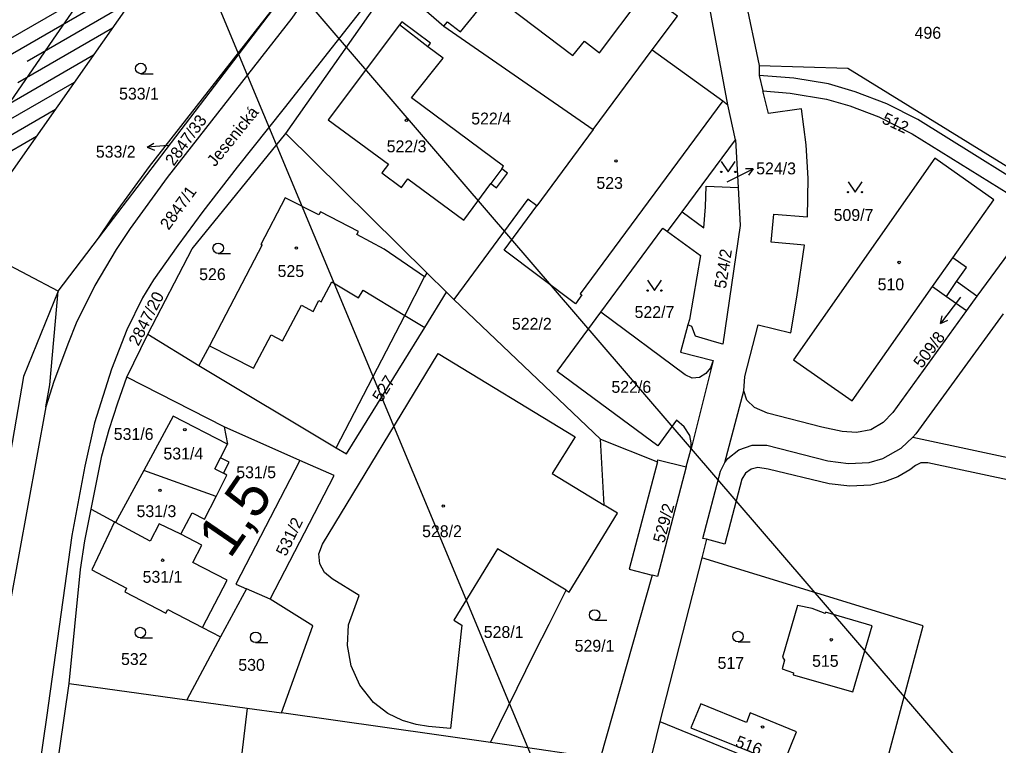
# Model space of a CAD drawing. Extents: x -558500 to -557517, y -1073973 to -1073051.
# Drawn here: x -558169.6 to -558029.6, y -1073540.5 to -1073436.6 of the extents above; entities that cross this region are included whole.
import ezdxf

# ---------------------------------------------------------------- set-up
doc = ezdxf.new("R2010")
doc.units = 0
for name, color, linetype in [('Hranice parcel', 7, 'Continuous'), ('Kolej', 7, 'Continuous'), ('Návěst místo trati', 7, 'Continuous'), ('Parcelní čísla', 7, 'Continuous'), ('Pop  PČ popisy', 7, 'Continuous'), ('Svazek obcí údolí Desné', 7, 'Continuous'), ('Vnitřní kresba', 7, 'Continuous'), ('Vrstva 28', 7, 'Continuous'), ('Značky budov', 7, 'Continuous'), ('Značky kultur', 7, 'Continuous')]:
    doc.layers.add(name, color=color, linetype=linetype)

msp = doc.modelspace()

# ---------------------------------------------------------------- linework, layer by layer
at = {"layer": 'Hranice parcel'}
for p, q in [((-558068.26, -1073448.76), (-558079.07, -1073390.9)), ((-558069.9, -1073413.89), (-558063.79, -1073443.12)), ((-558158.31, -1073467.84), (-558131.5, -1073432.67)), ((-558131.54, -1073452.88), (-558116.63, -1073431.7)), ((-558087.54, -1073452.3), (-558079.09, -1073440.91)), ((-558079.09, -1073440.91), (-558069.01, -1073448.19)), ((-558063.79, -1073443.12), (-558063.8, -1073444.57)), ((-558063.8, -1073444.57), (-558063.26, -1073446.76)), ((-558069.01, -1073448.19), (-558068.26, -1073448.76)), ((-558067.19, -1073453.76), (-558068.26, -1073448.76)), ((-558087.54, -1073452.3), (-558095.61, -1073463.24)), ((-558111.36, -1073472.82), (-558131.54, -1073452.88)), ((-558074.8, -1073464.07), (-558067.19, -1073453.76)), ((-558067.19, -1073453.76), (-558066.82, -1073460.61)), ((-558071.37, -1073460.39), (-558066.82, -1073460.61)), ((-558158.31, -1073467.84), (-558156.26, -1073464.79)), ((-558076.9, -1073466.92), (-558074.8, -1073464.07)), ((-558074.8, -1073464.07), (-558071.72, -1073466.37)), ((-558086.45, -1073478.46), (-558077.57, -1073466.44)), ((-558077.57, -1073466.44), (-558076.9, -1073466.92)), ((-558164.08, -1073475.42), (-558158.31, -1073467.84)), ((-558076.9, -1073466.92), (-558072.2, -1073470.34)), ((-558164.08, -1073475.42), (-558177.75, -1073468.29)), ((-558072.2, -1073470.34), (-558073.77, -1073479.5)), ((-558108.55, -1073475.6), (-558111.36, -1073472.82)), ((-558037.01, -1073476.18), (-558035.54, -1073474.05)), ((-558032.65, -1073476.17), (-558035.54, -1073474.05)), ((-558111.65, -1073480.62), (-558108.55, -1073475.6)), ((-558108.55, -1073475.6), (-558107.49, -1073476.62)), ((-558037.01, -1073476.18), (-558034.12, -1073478.2)), ((-558032.65, -1073476.17), (-558034.12, -1073478.2)), ((-558107.49, -1073476.62), (-558086.48, -1073496.61)), ((-558073.98, -1073480.28), (-558075.03, -1073484.15)), ((-558073.77, -1073479.5), (-558073.98, -1073480.28)), ((-558154.26, -1073487.77), (-558151.25, -1073481.61)), ((-558151.25, -1073481.61), (-558143.96, -1073486.09)), ((-558075.03, -1073484.15), (-558070.38, -1073485.35)), ((-558143.96, -1073486.09), (-558124.31, -1073497.86)), ((-558070.38, -1073485.35), (-558073.57, -1073498.15)), ((-558164.73, -1073488.39), (-558165.84, -1073492.01)), ((-558140.32, -1073494.88), (-558154.26, -1073487.77)), ((-558068.7, -1073499.98), (-558066, -1073489.71)), ((-558140.32, -1073494.88), (-558139.88, -1073497.35)), ((-558129.53, -1073499.66), (-558140.32, -1073494.88)), ((-558085.97, -1073506.08), (-558086.48, -1073496.61)), ((-558086.48, -1073496.61), (-558078.35, -1073499.89)), ((-558074.22, -1073500.6), (-558073.57, -1073498.15)), ((-558078.35, -1073499.89), (-558078.27, -1073499.57)), ((-558078.27, -1073499.57), (-558074.22, -1073500.6)), ((-558151.86, -1073501.13), (-558155.87, -1073508.56)), ((-558141.49, -1073504.81), (-558151.86, -1073501.13)), ((-558074.22, -1073500.6), (-558078.34, -1073516.28)), ((-558159.39, -1073506.66), (-558156.05, -1073508.46)), ((-558155.87, -1073508.56), (-558156.05, -1073508.46)), ((-558071.35, -1073510.96), (-558072, -1073513.63)), ((-558071.35, -1073510.96), (-558071.87, -1073510.83)), ((-558068.72, -1073511.63), (-558071.35, -1073510.96)), ((-558072, -1073513.63), (-558078.01, -1073537.04)), ((-558079.12, -1073516.08), (-558086.54, -1073542.34)), ((-558078.34, -1073516.28), (-558079.12, -1073516.08)), ((-558137.14, -1073518.03), (-558140.85, -1073524.92)), ((-558133.75, -1073519.51), (-558137.14, -1073518.03)), ((-558143.44, -1073523.57), (-558140.85, -1073524.92)), ((-558140.85, -1073524.92), (-558145.69, -1073533.93)), ((-558162.5, -1073531.6), (-558145.69, -1073533.93)), ((-558145.69, -1073533.93), (-558137.04, -1073535.13)), ((-558137.04, -1073535.13), (-558132.14, -1073535.81)), ((-558102.24, -1073540.03), (-558132.14, -1073535.81)), ((-558078.01, -1073537.04), (-558080.96, -1073549.01)), ((-558078.01, -1073537.04), (-558050.57, -1073548.21))]:
    msp.add_line(p, q, dxfattribs=at)
for points in [[(-558086.19, -1073392.25), (-558100.56, -1073410.01), (-558117.51, -1073431.08), (-558131.78, -1073449.27), (-558138.48, -1073457.68), (-558143.38, -1073464.02), (-558146.99, -1073468.89), (-558150.46, -1073473.83), (-558152.02, -1073476.41), (-558154.26, -1073480.97), (-558156.46, -1073486.6), (-558158.91, -1073494.31), (-558160.3, -1073500.48), (-558162.16, -1073510.4), (-558165.76, -1073536.46), (-558169.94, -1073565.43), (-558173.74, -1073591.61), (-558177.66, -1073620.33), (-558178.51, -1073631.87), (-558179.02, -1073643), (-558179.24, -1073655.12), (-558179.45, -1073666.94), (-558179.49, -1073675.4)], [(-558079.09, -1073440.91), (-558075.49, -1073436.06), (-558080.13, -1073432.64), (-558078.53, -1073430.7), (-558082.12, -1073428.01), (-558083.47, -1073429.99), (-558090.26, -1073424.91), (-558087.3, -1073420.92), (-558091.08, -1073418.03), (-558093.98, -1073421.97), (-558100.23, -1073417.28)], [(-558156.26, -1073464.79), (-558151.01, -1073457.58), (-558133.63, -1073435.37), (-558133.35, -1073433.74), (-558133.31, -1073429.98), (-558133.56, -1073429.34)], [(-558129.07, -1073430.81), (-558128.89, -1073431.83), (-558128.89, -1073432.84), (-558129.1, -1073433.85), (-558129.56, -1073434.77), (-558130.67, -1073436.36), (-558148.52, -1073459.19), (-558153.8, -1073466.46), (-558155.8, -1073469.46), (-558158.84, -1073474.63), (-558161.5, -1073480.01), (-558162.64, -1073482.78), (-558164.73, -1073488.39)], [(-558112.83, -1073434.1), (-558108.9, -1073437.49), (-558087.54, -1073452.3)], [(-558110.8, -1073439.94), (-558114.93, -1073436.89), (-558115.24, -1073437.31)], [(-558115.24, -1073437.31), (-558125.46, -1073450.9), (-558116.85, -1073457.27), (-558117.77, -1073458.51), (-558114.97, -1073460.58), (-558114.05, -1073459.35), (-558106.05, -1073465.28), (-558102.2, -1073460.05)], [(-558100.63, -1073457.93), (-558100.36, -1073457.56), (-558113.55, -1073447.75), (-558109, -1073442.11), (-558111.2, -1073440.45), (-558110.8, -1073439.94)], [(-558063.79, -1073443.12), (-558051.12, -1073443.51), (-558028.21, -1073457.62), (-558024.35, -1073450.45), (-558024.27, -1073448.53)], [(-558020.42, -1073463.73), (-558041.1, -1073450.88), (-558045.53, -1073448.61), (-558050.06, -1073446.9), (-558053.87, -1073445.77), (-558058.84, -1073444.97), (-558063.8, -1073444.57)], [(-558066, -1073489.71), (-558065.83, -1073487.66), (-558063.93, -1073480.27), (-558059.28, -1073481.39), (-558058.41, -1073476.28), (-558057.32, -1073468.85), (-558062.09, -1073468.41), (-558061.69, -1073464.41), (-558056.9, -1073464.79), (-558056.8, -1073459.32), (-558057.06, -1073454.51), (-558057.72, -1073449.34), (-558062.47, -1073450), (-558063.26, -1073446.76)], [(-558063.26, -1073446.76), (-558059.34, -1073447.1), (-558054.18, -1073447.94), (-558050.82, -1073448.92), (-558046.65, -1073450.5), (-558041.92, -1073452.93), (-558022.54, -1073464.96)], [(-558069.01, -1073448.19), (-558089.39, -1073475.8), (-558089.17, -1073475.95), (-558090.09, -1073477.27), (-558100.29, -1073469.58), (-558095.61, -1073463.24)], [(-558151.25, -1073481.61), (-558144.94, -1073469.39), (-558131.54, -1073452.88)], [(-558035.54, -1073474.05), (-558034.14, -1073472.03), (-558036.08, -1073470.66), (-558030.24, -1073462.37), (-558038.66, -1073456.4), (-558058.9, -1073485.25), (-558050.49, -1073491.12), (-558038.98, -1073474.78), (-558037.01, -1073476.18)], [(-558102.2, -1073460.05), (-558101.38, -1073460.67), (-558099.8, -1073458.54), (-558100.63, -1073457.93)], [(-558066.82, -1073460.61), (-558066.53, -1073466.05), (-558068.98, -1073483.05), (-558070.17, -1073482.68), (-558072.89, -1073481.86), (-558073.42, -1073480.5), (-558073.98, -1073480.28)], [(-558071.72, -1073466.37), (-558071.45, -1073463.36), (-558071.37, -1073460.39)], [(-558111.36, -1073472.82), (-558111.67, -1073473.41), (-558117.43, -1073469.44), (-558121.34, -1073467.34), (-558121.11, -1073466.9), (-558126.57, -1073464.07), (-558126.8, -1073464.51), (-558131.6, -1073462.08), (-558135.08, -1073468.74), (-558134.91, -1073468.83), (-558142.45, -1073483.25), (-558143.96, -1073486.09)], [(-558095.61, -1073463.24), (-558096.89, -1073462.29), (-558107.49, -1073476.62)], [(-558022.54, -1073464.96), (-558025.08, -1073466.74), (-558026.8, -1073468.19), (-558032.65, -1073476.17)], [(-558164.08, -1073475.42), (-558169.06, -1073487.65), (-558172.6, -1073507.93)], [(-558165.84, -1073492.01), (-558165.27, -1073488.87), (-558164.08, -1073475.42)], [(-558124.31, -1073497.86), (-558114.5, -1073478.9), (-558111.65, -1073480.62)], [(-558073.57, -1073498.15), (-558073.51, -1073497.13), (-558073.7, -1073496.11), (-558074.52, -1073494.85), (-558075.64, -1073493.89), (-558078.28, -1073497.56), (-558092.71, -1073486.96), (-558086.45, -1073478.46)], [(-558070.38, -1073485.35), (-558070.76, -1073486.43), (-558071.41, -1073487.24), (-558072.33, -1073487.8), (-558073.38, -1073487.88), (-558074.36, -1073487.41), (-558086.45, -1073478.46)], [(-558034.12, -1073478.2), (-558044.67, -1073492.79), (-558046.03, -1073494.25), (-558047.82, -1073495.28), (-558049.88, -1073495.66), (-558051.92, -1073495.51), (-558054.81, -1073494.91), (-558062.59, -1073492.91), (-558064.44, -1073492.11), (-558065.56, -1073491.04), (-558066, -1073489.71)], [(-558028.88, -1073478.68), (-558041.38, -1073495.88), (-558041.79, -1073496.35)], [(-558124.31, -1073497.86), (-558122.86, -1073498.73), (-558111.65, -1073480.62)], [(-558091.42, -1073518.26), (-558101.25, -1073512.3), (-558107.5, -1073522.55), (-558106.36, -1073523.27), (-558107.97, -1073538.05), (-558111.12, -1073537.73), (-558112.87, -1073537.48), (-558114.81, -1073536.91), (-558116.94, -1073535.87), (-558118.99, -1073534.32), (-558120.94, -1073531.84), (-558122.18, -1073529.05), (-558122.71, -1073526.18), (-558122.56, -1073523.2), (-558121.01, -1073518.98), (-558124.91, -1073516.6), (-558126.01, -1073515.72), (-558126.67, -1073514.49), (-558126.79, -1073513.04), (-558126.28, -1073511.65), (-558109.74, -1073484.35), (-558090.14, -1073496.27), (-558093.41, -1073501.56), (-558085.97, -1073506.08)], [(-558159.39, -1073506.66), (-558157.84, -1073498.99), (-558156.78, -1073495.22), (-558155.58, -1073491.43), (-558154.26, -1073487.77)], [(-558165.84, -1073492.01), (-558171, -1073520.22), (-558174.43, -1073545.49)], [(-558139.88, -1073497.35), (-558147.64, -1073493.32), (-558151.86, -1073501.13)], [(-558068.7, -1073499.98), (-558068.26, -1073499.37), (-558066.7, -1073498.15), (-558064.79, -1073497.48), (-558062.72, -1073497.49), (-558053.98, -1073499.73), (-558051.03, -1073500.12), (-558048.06, -1073499.96), (-558046.1, -1073499.41), (-558043.49, -1073497.93), (-558041.79, -1073496.35)], [(-558041.79, -1073496.35), (-558023.3, -1073500.28), (-558002.91, -1073505.27), (-557995.6, -1073507.26), (-557965.43, -1073516.64)], [(-558141.49, -1073504.81), (-558139.95, -1073501.78), (-558140.44, -1073501.51), (-558139.64, -1073499.94), (-558140.88, -1073499.3), (-558139.88, -1073497.35)], [(-558129.53, -1073499.66), (-558138.67, -1073517.37), (-558137.14, -1073518.03)], [(-558133.75, -1073519.51), (-558124.62, -1073501.83), (-558129.53, -1073499.66)], [(-558078.35, -1073499.89), (-558082.38, -1073515.23), (-558079.12, -1073516.08)], [(-558071.87, -1073510.83), (-558069.32, -1073501.19), (-558068.7, -1073499.98)], [(-557987.27, -1073529.77), (-557989.29, -1073528.94), (-557986.56, -1073522.48), (-557986.36, -1073521.52), (-557986.44, -1073520.51), (-557989.6, -1073512.4), (-557996.64, -1073510.25), (-558004.14, -1073508.22), (-558024.01, -1073503.35), (-558039.66, -1073500.03), (-558040.64, -1073500.03), (-558041.42, -1073500.4), (-558042.23, -1073501), (-558043.97, -1073502.01), (-558045.84, -1073502.74), (-558047.8, -1073503.22), (-558050.8, -1073503.37), (-558053.79, -1073503.03), (-558062.52, -1073500.9), (-558063.99, -1073500.68), (-558064.96, -1073500.91), (-558065.77, -1073501.48), (-558066.28, -1073502.33), (-558068.72, -1073511.63)], [(-558146.56, -1073510.24), (-558144.94, -1073507.17), (-558143.16, -1073508.08), (-558141.49, -1073504.81)], [(-558162.5, -1073531.6), (-558160.9, -1073515.3), (-558160.3, -1073511.2), (-558159.39, -1073506.66)], [(-558091.42, -1073518.26), (-558090.96, -1073518.54), (-558084.08, -1073507.23), (-558085.97, -1073506.08)], [(-558156.05, -1073508.46), (-558159.29, -1073515.35), (-558154.32, -1073517.94), (-558154.58, -1073518.47), (-558148.69, -1073521.52), (-558148.41, -1073520.99), (-558143.44, -1073523.57)], [(-558146.56, -1073510.24), (-558149.62, -1073508.74), (-558150.95, -1073511.21), (-558155.87, -1073508.56)], [(-558143.44, -1073523.57), (-558139.9, -1073516.83), (-558144.85, -1073514.28), (-558143.52, -1073511.79), (-558146.56, -1073510.24)], [(-558047.33, -1073549.53), (-558040.31, -1073523.33), (-558072, -1073513.63)], [(-558102.24, -1073540.03), (-558095.9, -1073527.13), (-558093.83, -1073523.1), (-558091.42, -1073518.26)], [(-558132.14, -1073535.81), (-558127.68, -1073523.33), (-558133.75, -1073519.51)], [(-558060.16, -1073528.26), (-558060.48, -1073529.48), (-558058.86, -1073530.06), (-558058.94, -1073530.35), (-558050.37, -1073532.81), (-558047.63, -1073523.32), (-558054.29, -1073521.4), (-558054.34, -1073521.59), (-558056.23, -1073520.85), (-558058.32, -1073520.45), (-558060.47, -1073527.85), (-558060.16, -1073528.26)], [(-558169.56, -1073582.12), (-558166.59, -1073559.69), (-558162.5, -1073531.6)], [(-558137.04, -1073535.13), (-558138.34, -1073545.94), (-558140.1, -1073559.78), (-558127.81, -1073561.38), (-558128.13, -1073563.82), (-558128.85, -1073568.77)], [(-558058.43, -1073538.53), (-558065.06, -1073535.79), (-558065.61, -1073537.16), (-558072.15, -1073534.51), (-558073.59, -1073537.94), (-558060.37, -1073543.23), (-558058.43, -1073538.53)], [(-558086.54, -1073542.34), (-558095.62, -1073541.02), (-558102.24, -1073540.03)]]:
    msp.add_lwpolyline(points, dxfattribs=at)
at = {"layer": 'Kolej'}
for points in [[(-558166.64, -1073442.09), (-558164.78, -1073439.38), (-558155.66, -1073426.13)], [(-558222.5, -1073523.52), (-558211.35, -1073507.26), (-558189.16, -1073474.89), (-558177.86, -1073458.42), (-558166.63, -1073442.09)]]:
    msp.add_lwpolyline(points, dxfattribs=at)
at = {"layer": 'Pop  PČ popisy'}
for p, q in [((-558151.36, -1073454.83), (-558150.41, -1073454.25)), ((-558148.37, -1073454.57), (-558151.36, -1073454.83)), ((-558151.36, -1073454.83), (-558150.32, -1073455.24)), ((-558067.34, -1073459.26), (-558064.64, -1073457.94)), ((-558064.64, -1073457.94), (-558065.76, -1073457.93)), ((-558064.64, -1073457.94), (-558065.32, -1073458.83)), ((-558068.37, -1073459.77), (-558067.34, -1073459.26)), ((-558035, -1073476.29), (-558036.02, -1073477.67)), ((-558036.02, -1073477.67), (-558037.83, -1073480.07)), ((-558037.83, -1073480.07), (-558037.62, -1073478.97)), ((-558037.83, -1073480.07), (-558036.82, -1073479.57))]:
    msp.add_line(p, q, dxfattribs=at)
at = {"layer": 'Svazek obcí údolí Desné'}
for p, q in [((-558138.47, -1073412.32), (-558177.75, -1073468.29)), ((-558173.52, -1073440.75), (-558148.14, -1073426.1)), ((-558176, -1073444.49), (-558150.86, -1073429.98)), ((-558168.55, -1073442.5), (-558153.59, -1073433.86)), ((-558169.85, -1073445.56), (-558156.31, -1073437.74)), ((-558183.42, -1073455.7), (-558159.04, -1073441.63)), ((-558185.89, -1073459.44), (-558161.76, -1073445.51)), ((-558188.37, -1073463.18), (-558164.49, -1073449.39)), ((-558190.84, -1073466.92), (-558167.21, -1073453.27))]:
    msp.add_line(p, q, dxfattribs=at)
at = {"layer": 'Vnitřní kresba'}
for p, q in [((-558106.53, -1073438.34), (-558102.09, -1073432.87)), ((-558102.09, -1073432.87), (-558090.44, -1073441.72)), ((-558086.64, -1073441.31), (-558080.13, -1073432.64)), ((-558108.9, -1073437.49), (-558108.41, -1073436.89)), ((-558108.41, -1073436.89), (-558106.53, -1073438.34)), ((-558111.2, -1073440.45), (-558115.24, -1073437.31)), ((-558090.44, -1073441.72), (-558088.8, -1073439.66)), ((-558088.8, -1073439.66), (-558086.64, -1073441.31)), ((-558100.63, -1073457.93), (-558102.2, -1073460.05)), ((-558038.98, -1073474.78), (-558036.08, -1073470.66)), ((-558114.5, -1073478.9), (-558111.67, -1073473.41)), ((-558126.45, -1073476.96), (-558124.93, -1073474.1)), ((-558124.93, -1073474.1), (-558121.12, -1073476.4)), ((-558121.12, -1073476.4), (-558120.46, -1073475.31)), ((-558120.46, -1073475.31), (-558114.5, -1073478.9)), ((-558132, -1073482.54), (-558129.3, -1073477.44)), ((-558129.3, -1073477.44), (-558127.63, -1073478.35)), ((-558127.63, -1073478.35), (-558126.79, -1073476.79)), ((-558126.79, -1073476.79), (-558126.45, -1073476.96)), ((-558136.15, -1073486.45), (-558133.63, -1073481.7)), ((-558133.63, -1073481.7), (-558132, -1073482.54)), ((-558142.45, -1073483.25), (-558136.15, -1073486.45)), ((-558141.68, -1073500.85), (-558140.88, -1073499.3)), ((-558141.68, -1073500.85), (-558140.44, -1073501.51))]:
    msp.add_line(p, q, dxfattribs=at)
at = {"layer": 'Vrstva 28'}
for p, q in [((-558150.5, -1073408.33), (-557941.76, -1073651.48)), ((-558150.16, -1073413.05), (-558044.9, -1073665.43))]:
    msp.add_line(p, q, dxfattribs=at)
at = {"layer": 'Značky budov'}
for centre in [(-558114.25, -1073450.97), (-558084.29, -1073456.8), (-558130.01, -1073469.27), (-558043.77, -1073471.33), (-558145.97, -1073495.27), (-558149.53, -1073503.95), (-558108.99, -1073506.2), (-558149.15, -1073513.95), (-558053.47, -1073525.34), (-558063.31, -1073537.83)]:
    msp.add_circle(centre, 0.175, dxfattribs=at)
at = {"layer": 'Značky kultur'}
for p, q in [((-558152.27, -1073444.31), (-558150.52, -1073444.31)), ((-558141.2, -1073470.05), (-558139.45, -1073470.05)), ((-558087.33, -1073522.53), (-558085.58, -1073522.53)), ((-558152.35, -1073525.05), (-558150.6, -1073525.05)), ((-558135.84, -1073525.74), (-558134.09, -1073525.74)), ((-558066.82, -1073525.63), (-558065.07, -1073525.63))]:
    msp.add_line(p, q, dxfattribs=at)
for points in [[(-558069.21, -1073456.87), (-558068.21, -1073458.37), (-558067.21, -1073456.87)], [(-558051.07, -1073459.77), (-558050.07, -1073461.27), (-558049.07, -1073459.77)], [(-558079.77, -1073473.86), (-558078.77, -1073475.36), (-558077.77, -1073473.86)]]:
    msp.add_lwpolyline(points, dxfattribs=at)
for centre, radius in [((-558152.27, -1073443.56), 0.75), ((-558069.21, -1073458.37), 0.1), ((-558067.21, -1073458.37), 0.1), ((-558051.07, -1073461.27), 0.1), ((-558049.07, -1073461.27), 0.1), ((-558141.2, -1073469.3), 0.75), ((-558079.77, -1073475.36), 0.1), ((-558077.77, -1073475.36), 0.1), ((-558087.33, -1073521.78), 0.75), ((-558152.35, -1073524.3), 0.75), ((-558135.84, -1073524.99), 0.75), ((-558066.82, -1073524.88), 0.75)]:
    msp.add_circle(centre, radius, dxfattribs=at)

# ---------------------------------------------------------------- texts
at = {"layer": 'Návěst místo trati'}
msp.add_text('1,5', height=6, rotation=55.5626, dxfattribs=at).set_placement((-558139.51, -1073513.88))
at = {"layer": 'Parcelní čísla'}
for s, p in [('496', (-558041.55, -1073439.31)), ('533/1', (-558155.38, -1073448.02)), ('522/4', (-558104.99, -1073451.58)), ('522/3', (-558117.09, -1073455.56)), ('533/2', (-558158.7, -1073456.33)), ('524/3', (-558064.22, -1073458.72)), ('523', (-558087.08, -1073460.8)), ('509/7', (-558053.14, -1073465.39)), ('525', (-558132.7, -1073473.41)), ('526', (-558143.92, -1073473.86)), ('510', (-558046.84, -1073475.32)), ('522/7', (-558081.62, -1073479.28)), ('522/2', (-558099.17, -1073480.96)), ('522/6', (-558084.93, -1073489.99)), ('531/6', (-558156.14, -1073496.74)), ('531/4', (-558149.03, -1073499.53)), ('531/5', (-558138.61, -1073502.21)), ('531/3', (-558152.88, -1073507.78)), ('528/2', (-558112.02, -1073510.65)), ('531/1', (-558152.01, -1073517.18)), ('528/1', (-558103.2, -1073525.08)), ('529/1', (-558090.19, -1073527.05)), ('532', (-558155.1, -1073528.95)), ('530', (-558138.32, -1073529.78)), ('517', (-558069.74, -1073529.5)), ('515', (-558056.22, -1073529.21))]:
    msp.add_text(s, height=1.7, dxfattribs=at).set_placement(p)
for s, rotation, p in [('2847/33', 54, (-558147.56, -1073457.63)), ('512', 335, (-558046.36, -1073451.33)), ('2847/1', 54, (-558148.29, -1073466.81)), ('524/2', 81, (-558068.56, -1073475.16)), ('2847/20', 63, (-558152.61, -1073483.4)), ('509/8', 53, (-558040.52, -1073486.58)), ('527', 58, (-558117.82, -1073491.43)), ('529/2', 75, (-558077.38, -1073511.59)), ('531/2', 64, (-558131.51, -1073513.5)), ('516', 339, (-558067.34, -1073540.57))]:
    msp.add_text(s, height=1.7, rotation=rotation, dxfattribs=at).set_placement(p)
at = {"layer": 'Pop  PČ popisy'}
msp.add_text('Jesenická', height=1.7, rotation=51, dxfattribs=at).set_placement((-558141.65, -1073457.73))

doc.saveas('drawing.dxf')
